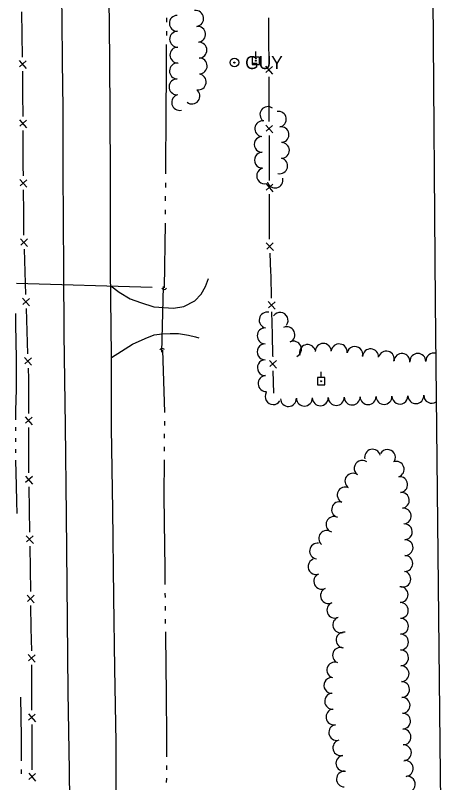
# Model space of a CAD drawing. Extents: x 589250 to 1188077, y 162953 to 363065.
# Drawn here: x 594342.5 to 594542.1, y 167438.7 to 167794 of the extents above; entities that cross this region are included whole.
import ezdxf

# ---------------------------------------------------------------- set-up
doc = ezdxf.new("R2010")
doc.units = 0
for name, color, linetype in [('E_DRN', 7, 'Continuous'), ('E_DRN_Pipe', 7, 'Continuous'), ('E_DWY', 7, 'Continuous'), ('E_FEN_P', 7, 'Continuous'), ('E_LAND_TreeLine_P', 7, 'Continuous'), ('E_MAP_Limits', 7, 'Continuous'), ('E_RDWY', 7, 'Continuous'), ('E_UTL_EGuyWire', 7, 'Continuous'), ('E_UTL_EPowerPole', 7, 'Continuous'), ('E_WTR_FlowLine', 7, 'Continuous')]:
    doc.layers.add(name, color=color, linetype=linetype)

msp = doc.modelspace()

# ---------------------------------------------------------------- linework, layer by layer
at = {"layer": 'E_DRN'}
for centre, start, end in [((594411.32, 167668.43), 218.2211, 324.4813), ((594410.48, 167638.34), 41.7975, 148.0577)]:
    msp.add_arc(centre, 1.34, start, end, dxfattribs=at)
at = {"layer": 'E_DRN_Pipe'}
for p, q in [((594342.98, 167670.02), (594405.75, 167668.17)), ((594410.87, 167668.48), (594410.07, 167638.04))]:
    msp.add_line(p, q, dxfattribs=at)
at = {"layer": 'E_DWY'}
for p, q in [((594430.55, 167668.4), (594431.87, 167672.11)), ((594386.67, 167668.71), (594390.58, 167665.72)), ((594390.58, 167665.72), (594395.6, 167662.7)), ((594428.56, 167664.81), (594430.55, 167668.4)), ((594395.6, 167662.7), (594400.45, 167661.08)), ((594420.48, 167659.14), (594425.63, 167661.81)), ((594425.63, 167661.81), (594428.56, 167664.81)), ((594400.45, 167661.08), (594406.58, 167659.02)), ((594406.58, 167659.02), (594415.68, 167658.36)), ((594415.68, 167658.36), (594420.48, 167659.14)), ((594396.76, 167641.74), (594402.51, 167644.35)), ((594402.51, 167644.35), (594406.69, 167645.99)), ((594406.69, 167645.99), (594410.42, 167646.54)), ((594410.42, 167646.54), (594414.22, 167646.63)), ((594414.22, 167646.63), (594418.03, 167646.59)), ((594418.03, 167646.59), (594422.66, 167645.9)), ((594422.66, 167645.9), (594425.96, 167645.04)), ((594425.96, 167645.04), (594427.44, 167644.61)), ((594391.56, 167638.48), (594396.76, 167641.74)), ((594386.94, 167635.57), (594391.56, 167638.48))]:
    msp.add_line(p, q, dxfattribs=at)
at = {"layer": 'E_FEN_P'}
for p, q in [((594345.36, 167795.67), (594345.54, 167785.17)), ((594459.67, 167792.82), (594459.73, 167782.42)), ((594345.54, 167785.17), (594345.72, 167774.67)), ((594459.73, 167782.42), (594459.8, 167772.02)), ((594344.28, 167773.03), (594347.52, 167769.42)), ((594347.46, 167772.91), (594344.39, 167770.11)), ((594458.35, 167770.41), (594461.53, 167766.81)), ((594461.5, 167770.27), (594458.43, 167767.52)), ((594345.8, 167768.17), (594345.85, 167757.66)), ((594459.84, 167765.58), (594459.84, 167764.46)), ((594459.84, 167764.46), (594459.87, 167755.18)), ((594345.85, 167757.66), (594345.89, 167747.16)), ((594459.87, 167755.18), (594459.9, 167744.78)), ((594344.43, 167745.54), (594347.63, 167741.9)), ((594347.62, 167745.39), (594344.51, 167742.62)), ((594345.92, 167740.66), (594345.97, 167730.16)), ((594458.45, 167743.18), (594461.61, 167739.57)), ((594461.6, 167743.02), (594458.52, 167740.29)), ((594459.92, 167738.35), (594459.95, 167727.95)), ((594345.97, 167730.16), (594346, 167724.18)), ((594459.95, 167727.95), (594459.98, 167717.55)), ((594346, 167724.18), (594346.04, 167719.66)), ((594344.58, 167718.03), (594347.8, 167714.4)), ((594347.77, 167717.89), (594344.67, 167715.11)), ((594458.52, 167715.94), (594461.69, 167712.33)), ((594461.68, 167715.79), (594458.6, 167713.05)), ((594346.1, 167713.16), (594346.19, 167702.65)), ((594460, 167711.11), (594460.03, 167700.71)), ((594346.19, 167702.65), (594346.27, 167693.11)), ((594460.03, 167700.71), (594460.05, 167690.31)), ((594344.88, 167690.49), (594348.19, 167686.94)), ((594348.07, 167690.43), (594345.05, 167687.57)), ((594346.27, 167693.11), (594346.3, 167692.15)), ((594458.66, 167688.65), (594461.96, 167685.16)), ((594461.82, 167688.62), (594458.85, 167685.76)), ((594346.52, 167685.66), (594346.87, 167675.16)), ((594460.32, 167683.88), (594460.68, 167675.06)), ((594346.87, 167675.16), (594347.22, 167664.66)), ((594460.68, 167675.06), (594460.72, 167673.49)), ((594460.72, 167673.49), (594460.96, 167663.09)), ((594345.8, 167663), (594349.11, 167659.45)), ((594348.99, 167662.94), (594345.97, 167660.08)), ((594347.44, 167658.17), (594347.79, 167647.67)), ((594459.55, 167661.45), (594462.78, 167657.91)), ((594462.7, 167661.36), (594459.68, 167658.57)), ((594461.12, 167656.65), (594461.36, 167646.26)), ((594347.79, 167647.67), (594348.14, 167637.17)), ((594461.36, 167646.26), (594461.59, 167636.53)), ((594346.72, 167635.51), (594350.03, 167631.96)), ((594349.91, 167635.45), (594346.89, 167632.59)), ((594460.18, 167634.23), (594463.41, 167630.67)), ((594463.34, 167634.13), (594460.3, 167631.34)), ((594461.59, 167636.53), (594461.61, 167635.86)), ((594348.36, 167630.68), (594348.53, 167625.67)), ((594461.73, 167629.42), (594461.94, 167619.03)), ((594348.53, 167625.67), (594348.54, 167620.18)), ((594348.54, 167620.18), (594348.57, 167609.68)), ((594347.1, 167608.06), (594350.3, 167604.41)), ((594350.29, 167607.9), (594347.17, 167605.14)), ((594348.58, 167603.17), (594348.61, 167592.67)), ((594348.61, 167592.67), (594348.64, 167582.17)), ((594347.17, 167580.55), (594350.37, 167576.9)), ((594350.36, 167580.39), (594347.24, 167577.63)), ((594348.69, 167575.67), (594348.85, 167565.17)), ((594348.85, 167565.17), (594349.02, 167554.67)), ((594347.57, 167553.03), (594350.82, 167549.42)), ((594350.76, 167552.91), (594347.69, 167550.11)), ((594349.12, 167548.17), (594349.29, 167537.67)), ((594349.29, 167537.67), (594349.46, 167527.17)), ((594348.01, 167525.53), (594351.25, 167521.92)), ((594351.2, 167525.41), (594348.12, 167522.61)), ((594349.56, 167520.67), (594349.73, 167510.17)), ((594349.73, 167510.17), (594349.89, 167499.72)), ((594349.89, 167499.72), (594349.89, 167499.66)), ((594348.43, 167498.04), (594351.63, 167494.4)), ((594351.62, 167497.89), (594348.51, 167495.12)), ((594349.92, 167493.16), (594349.97, 167482.66)), ((594349.97, 167482.66), (594350.02, 167472.16)), ((594348.55, 167470.54), (594351.76, 167466.89)), ((594351.74, 167470.38), (594348.63, 167467.62)), ((594350.05, 167465.66), (594350.1, 167455.16)), ((594350.1, 167455.16), (594350.14, 167444.65)), ((594348.68, 167443.03), (594351.88, 167439.39)), ((594351.86, 167442.88), (594348.76, 167440.11))]:
    msp.add_line(p, q, dxfattribs=at)
at = {"layer": 'E_LAND_TreeLine_P'}
for centre, radius, start, end in [((594417.47, 167790.3), 3.68, 90.9997, 270.9997), ((594425.96, 167792.53), 3.68, 278.194, 98.194), ((594417.6, 167782.94), 3.68, 90.9997, 270.9997), ((594426.87, 167785.23), 3.68, 276.4744, 96.4744), ((594417.72, 167775.58), 3.68, 90.9997, 270.9997), ((594427.48, 167777.9), 3.68, 271.0648, 91.0648), ((594417.53, 167768.22), 3.68, 88.2636, 268.2636), ((594427.61, 167770.54), 3.68, 271.0648, 91.0648), ((594427.12, 167763.15), 3.68, 261.1892, 81.1892), ((594417.31, 167760.87), 3.68, 88.2636, 268.2636), ((594424.23, 167756.64), 3.68, 232.2574, 52.2574), ((594418.54, 167753.66), 3.68, 103.9514, 283.9514), ((594459.37, 167748.07), 3.64, 52.8211, 232.8211), ((594464.29, 167745.89), 3.64, 279.7782, 99.7782), ((594456.96, 167741.46), 3.64, 82.3495, 262.3495), ((594465.52, 167738.73), 3.64, 279.7782, 99.7782), ((594456.7, 167734.21), 3.64, 91.1053, 271.1053), ((594465.7, 167731.46), 3.64, 270.9886, 90.9886), ((594456.84, 167726.94), 3.64, 91.1053, 271.1053), ((594464.89, 167724.29), 3.64, 256.3241, 76.3241), ((594457.86, 167719.66), 3.64, 105.112, 285.112), ((594462.71, 167717.68), 3.64, 194.2262, 14.2262), ((594459.06, 167652.86), 3.69, 77.7008, 257.7008), ((594465.04, 167652.72), 3.69, 324.0473, 144.0473), ((594458.14, 167645.57), 3.69, 88.8617, 268.8617), ((594468.17, 167646.09), 3.69, 294.9806, 114.9806), ((594458.12, 167638.2), 3.69, 90.3964, 270.3964), ((594471.25, 167639.39), 3.69, 294.4576, 114.4576), ((594477.71, 167637.82), 3.69, 18.1726, 198.1726), ((594485.03, 167638.38), 3.69, 0.7352, 180.7352), ((594492.38, 167638.13), 3.69, 353.0541, 173.0541), ((594499.65, 167636.92), 3.69, 347.6799, 167.6799), ((594506.93, 167635.85), 3.69, 356.8763, 176.8763), ((594514.19, 167634.83), 3.69, 344.0854, 164.0854), ((594521.45, 167633.72), 3.69, 354.6846, 174.6846), ((594528.82, 167633.74), 3.69, 0.3001, 180.3001), ((594536.2, 167633.92), 3.69, 76.1729, 181.3512), ((594458.24, 167630.82), 3.69, 91.3512, 271.3512), ((594458.55, 167623.46), 3.69, 93.3966, 273.3966), ((594461.8, 167617.41), 3.69, 149.4431, 329.4431), ((594468.91, 167616.56), 3.69, 181.3512, 1.3512), ((594476.28, 167616.73), 3.69, 181.3512, 1.3512), ((594483.65, 167616.9), 3.69, 180.9361, 0.9361), ((594491.03, 167617.02), 3.69, 180.9361, 0.9361), ((594498.4, 167617.24), 3.69, 181.8287, 1.8287), ((594505.77, 167617.43), 3.69, 181.3512, 1.3512), ((594513.15, 167617.54), 3.69, 180.8351, 0.8351), ((594520.52, 167617.66), 3.69, 180.8854, 0.8854), ((594527.89, 167617.9), 3.69, 182.2535, 2.2535), ((594535.27, 167618.06), 3.69, 180.5443, 303.7531), ((594507.85, 167589.4), 3.66, 13.402, 193.402), ((594514.74, 167589.3), 3.66, 331.3463, 151.3463), ((594503.02, 167584.23), 3.66, 53.6182, 233.6182), ((594518.8, 167583.77), 3.66, 289.6366, 109.6366), ((594498.74, 167578.28), 3.66, 54.3941, 234.3941), ((594520.42, 167576.68), 3.66, 275.876, 95.876), ((594495.16, 167571.91), 3.66, 63.8768, 243.8768), ((594521.2, 167569.39), 3.66, 276.9872, 96.9872), ((594492.56, 167565.08), 3.66, 72.2577, 252.2577), ((594522.09, 167562.12), 3.66, 276.9872, 96.9872), ((594490.01, 167558.23), 3.66, 65.1897, 245.1897), ((594486.6, 167551.79), 3.66, 50.6987, 230.6987), ((594522.59, 167554.82), 3.66, 273.2394, 93.2394), ((594482.37, 167545.94), 3.66, 82.1402, 262.1402), ((594522.91, 167547.5), 3.66, 269.0606, 89.0606), ((594481.68, 167538.72), 3.66, 111.0384, 291.0384), ((594522.79, 167540.17), 3.66, 269.0606, 89.0606), ((594484.33, 167531.89), 3.66, 114.9806, 294.9806), ((594521.89, 167532.93), 3.66, 258.1937, 78.1937), ((594487.42, 167525.25), 3.66, 114.9806, 294.9806), ((594520.6, 167525.74), 3.66, 271.0329, 91.0329), ((594490.38, 167518.55), 3.66, 112.2987, 292.2987), ((594520.73, 167518.42), 3.66, 271.0329, 91.0329), ((594493.07, 167511.74), 3.66, 108.2564, 288.2564), ((594520.8, 167511.09), 3.66, 269.9764, 89.9764), ((594494.64, 167504.71), 3.66, 81.7911, 261.7911), ((594520.79, 167503.77), 3.66, 269.8824, 89.8824), ((594492.98, 167497.63), 3.66, 67.237, 247.237), ((594520.84, 167496.44), 3.66, 271.7464, 91.7464), ((594490.33, 167490.81), 3.66, 72.5732, 252.5732), ((594521.06, 167489.12), 3.66, 271.7464, 91.7464), ((594488.95, 167483.71), 3.66, 92.339, 272.339), ((594521.3, 167481.79), 3.66, 271.8409, 91.8409), ((594489.33, 167476.39), 3.66, 94.5061, 274.5061), ((594521.53, 167474.47), 3.66, 271.8409, 91.8409), ((594489.98, 167469.1), 3.66, 100.1641, 280.1641), ((594521.75, 167467.15), 3.66, 271.7105, 91.7105), ((594491.27, 167461.89), 3.66, 100.1641, 280.1641), ((594521.97, 167459.82), 3.66, 271.7105, 91.7105), ((594493.16, 167454.81), 3.66, 105.3875, 285.3875), ((594522.19, 167452.5), 3.66, 271.7105, 91.7105), ((594494.58, 167447.63), 3.66, 100.4983, 280.4983), ((594523, 167445.22), 3.66, 276.8068, 96.8068), ((594494.82, 167440.33), 3.66, 89.3299, 269.3299), ((594523.97, 167437.96), 3.66, 279.6336, 99.6336)]:
    msp.add_arc(centre, radius, start, end, dxfattribs=at)
at = {"layer": 'E_MAP_Limits'}
for p, q in [((594535.49, 167836.99), (594536.83, 167661.12)), ((594536.83, 167661.12), (594539.12, 167442.44)), ((594539.12, 167442.44), (594542.15, 167249.29))]:
    msp.add_line(p, q, dxfattribs=at)
at = {"layer": 'E_RDWY'}
for p, q in [((594363.65, 167819.7), (594363.97, 167791.9)), ((594386.18, 167773.47), (594385.67, 167820.31)), ((594363.97, 167791.9), (594364.23, 167772.53)), ((594364.23, 167772.53), (594364.4, 167750.94)), ((594386.54, 167721.14), (594386.18, 167773.47)), ((594364.4, 167750.94), (594364.41, 167722.27)), ((594364.41, 167722.27), (594364.63, 167698.82)), ((594386.6, 167676.16), (594386.54, 167721.14)), ((594364.63, 167698.82), (594364.76, 167676.23)), ((594364.76, 167676.23), (594364.99, 167646.57)), ((594386.94, 167636.47), (594386.6, 167676.16)), ((594364.99, 167646.57), (594365.53, 167603.94)), ((594387.06, 167602.79), (594386.94, 167636.47)), ((594365.53, 167603.94), (594366.04, 167562.58)), ((594387.62, 167565.05), (594387.06, 167602.79)), ((594366.04, 167562.58), (594366.44, 167514.22)), ((594388.04, 167524.49), (594387.62, 167565.05)), ((594388.49, 167491.6), (594388.04, 167524.49)), ((594366.44, 167514.22), (594366.83, 167480.68)), ((594389.09, 167457.46), (594388.49, 167491.6)), ((594366.83, 167480.68), (594367.35, 167444.34)), ((594389.28, 167415.36), (594389.09, 167457.46)), ((594367.35, 167444.34), (594367.65, 167414.67))]:
    msp.add_line(p, q, dxfattribs=at)
at = {"layer": 'E_UTL_EGuyWire'}
for radius in [2, 0.25]:
    msp.add_circle((594443.88, 167772.11), radius, dxfattribs=at)
at = {"layer": 'E_UTL_EPowerPole'}
for points in [[(594453.77, 167774.65), (594453.77, 167777.3)], [(594455.44, 167774.65), (594452.09, 167774.65)], [(594452.09, 167774.65), (594452.09, 167771.3)], [(594455.44, 167771.3), (594455.44, 167774.65)], [(594452.09, 167771.3), (594455.44, 167771.3)], [(594485.69, 167626.24), (594482.34, 167626.24)], [(594482.34, 167626.24), (594482.34, 167622.88)], [(594484.01, 167626.24), (594484.01, 167628.88)], [(594485.69, 167622.88), (594485.69, 167626.24)], [(594482.34, 167622.88), (594485.69, 167622.88)]]:
    msp.add_lwpolyline(points, dxfattribs=at)
for centre in [(594453.8, 167772.98), (594484.04, 167624.56)]:
    msp.add_circle(centre, 0.217, dxfattribs=at)
at = {"layer": 'E_WTR_FlowLine'}
for p, q in [((594412.48, 167792.85), (594412.46, 167790.79)), ((594412.43, 167786.65), (594412.41, 167784.59)), ((594412.38, 167780.45), (594412.27, 167765.76)), ((594412.27, 167765.76), (594412.17, 167750.49)), ((594412.17, 167750.49), (594411.99, 167720.52)), ((594411.96, 167716.39), (594411.95, 167714.32)), ((594411.91, 167710.19), (594411.89, 167708.12)), ((594411.84, 167703.99), (594411.82, 167701.93)), ((594411.77, 167697.79), (594411.44, 167667.83)), ((594342.49, 167655.93), (594342.61, 167650.75)), ((594342.61, 167650.75), (594342.85, 167635.12)), ((594410.58, 167639), (594411.53, 167610.16)), ((594342.85, 167635.12), (594342.85, 167631.3)), ((594342.85, 167631.3), (594342.85, 167620.75)), ((594342.85, 167620.75), (594342.55, 167611.05)), ((594342.55, 167611.05), (594342.53, 167606.67)), ((594411.53, 167610.16), (594411.53, 167610.11)), ((594411.5, 167606.13), (594411.48, 167604.13)), ((594342.53, 167603.27), (594342.52, 167601.57)), ((594342.51, 167598.17), (594342.51, 167596.47)), ((594411.45, 167600.15), (594411.44, 167598.15)), ((594411.41, 167594.17), (594411.39, 167592.17)), ((594342.52, 167593.07), (594342.52, 167591.38)), ((594342.56, 167587.98), (594342.83, 167576.17)), ((594411.36, 167588.19), (594411.23, 167571.79)), ((594342.83, 167576.17), (594343.01, 167568.89)), ((594411.23, 167571.79), (594411.38, 167559.28)), ((594343.01, 167568.89), (594343.14, 167563.35)), ((594411.38, 167559.28), (594411.63, 167537.91)), ((594411.63, 167537.91), (594411.71, 167530.38)), ((594411.75, 167526.39), (594411.77, 167524.4)), ((594411.82, 167520.41), (594411.84, 167518.42)), ((594411.88, 167514.43), (594411.9, 167512.44)), ((594411.94, 167508.45), (594411.96, 167506.98)), ((594411.96, 167506.98), (594412.26, 167479.55)), ((594345.31, 167459.94), (594345.08, 167478.31)), ((594412.26, 167479.55), (594412.48, 167459.47)), ((594345.34, 167448.82), (594345.31, 167459.94)), ((594412.48, 167459.47), (594412.44, 167450.64)), ((594412.42, 167446.66), (594412.41, 167444.66)), ((594345.36, 167442.71), (594345.35, 167444.75)), ((594412.39, 167440.68), (594412.38, 167438.68))]:
    msp.add_line(p, q, dxfattribs=at)

# ---------------------------------------------------------------- texts
at = {"layer": 'E_UTL_EGuyWire'}
msp.add_text('GUY', height=6, dxfattribs=at).set_placement((594448.88, 167769.11))

doc.saveas('drawing.dxf')
